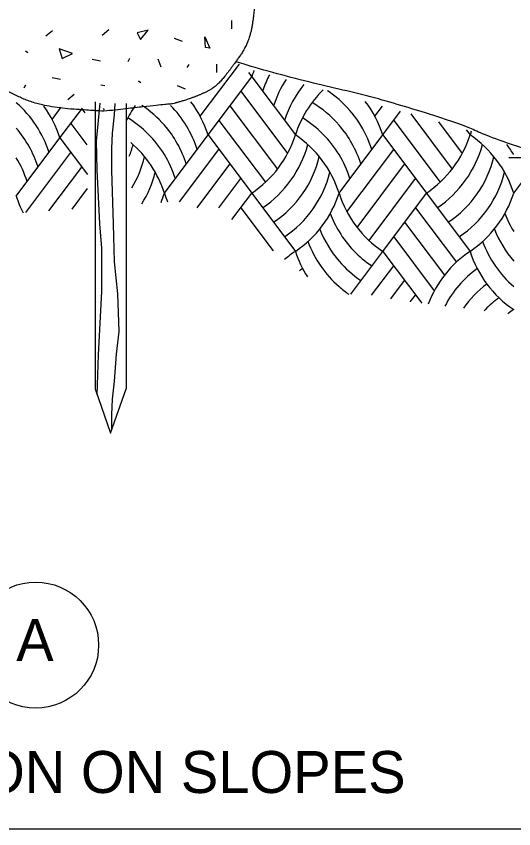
# Model space of a CAD drawing. Extents: x 99862 to 103680, y 99470 to 102076.
# Drawn here: x 101727.5 to 101964.3, y 99999.5 to 100386.5 of the extents above; entities that cross this region are included whole.
import ezdxf

# ---------------------------------------------------------------- set-up
doc = ezdxf.new("R2010")
doc.units = 0
for name, color, linetype in [('Level 1', 7, 'Continuous'), ('Level 13', 7, 'Continuous'), ('Level 2', 7, 'Continuous'), ('Level 20', 7, 'Continuous'), ('Level 3', 7, 'Continuous'), ('Level 4', 7, 'Continuous')]:
    doc.layers.add(name, color=color, linetype=linetype)

msp = doc.modelspace()

# ---------------------------------------------------------------- linework, layer by layer
at = {"layer": 'Level 1'}
msp.add_lwpolyline([(99862, 99999.5), (103151, 99999.5), (103151, 102075.5), (99862, 102075.5)], close=True, dxfattribs=at)
at = {"layer": 'Level 13'}
for p, q in [((101815.06, 100338.81), (101833.69, 100363.65)), ((101838.12, 100359.62), (101839.59, 100357.66)), ((101818.8, 100329.94), (101839.59, 100357.66)), ((101839.59, 100357.66), (101860.38, 100329.94)), ((101834.4, 100350.73), (101856.64, 100321.07)), ((101744.52, 100337.37), (101748.91, 100343.22)), ((101748.27, 100328.5), (101758.97, 100342.77)), ((101829.2, 100343.8), (101851.82, 100313.64)), ((101898.22, 100338.81), (101901.86, 100343.67)), ((101758.66, 100342.36), (101760.07, 100340.48)), ((101768.89, 100342.58), (101769.4, 100341.9)), ((101901.96, 100329.94), (101910.47, 100341.28)), ((101915.26, 100339.93), (101934.97, 100313.64)), ((101753.47, 100335.43), (101761.11, 100325.24)), ((101824, 100336.87), (101846.11, 100307.39)), ((101907.16, 100336.87), (101929.26, 100307.39)), ((101928.49, 100336.15), (101939.79, 100321.07)), ((101941.72, 100332.36), (101943.54, 100329.94)), ((101727.48, 100300.78), (101748.27, 100328.5)), ((101748.27, 100328.5), (101761.34, 100311.08)), ((101798.01, 100302.22), (101818.8, 100329.94)), ((101818.8, 100329.94), (101839.59, 100302.22)), ((101881.17, 100302.22), (101901.96, 100329.94)), ((101901.96, 100329.94), (101922.75, 100302.22)), ((101732.01, 100292.96), (101753.47, 100321.57)), ((101805.25, 100298.01), (101824, 100323.01)), ((101884.91, 100293.35), (101907.16, 100323.01)), ((101813.56, 100295.23), (101829.2, 100316.08)), ((101889.74, 100285.92), (101912.35, 100316.08)), ((101964.33, 100302.22), (101976.89, 100318.97)), ((101743.03, 100293.79), (101758.66, 100314.64)), ((101823.96, 100295.23), (101834.4, 100309.15)), ((101895.44, 100279.67), (101917.55, 100309.15)), ((101754.05, 100294.62), (101761.36, 100304.38)), ((101830.19, 100289.69), (101839.59, 100302.22)), ((101839.59, 100302.22), (101860.38, 100274.5)), ((101901.96, 100274.5), (101922.75, 100302.22)), ((101922.75, 100302.22), (101943.54, 100274.5)), ((101834.4, 100295.29), (101849.81, 100274.74)), ((101917.55, 100295.29), (101937.02, 100269.33)), ((101912.35, 100288.36), (101931.31, 100263.08)), ((101907.16, 100281.43), (101926.49, 100255.65)), ((101886.69, 100254.14), (101901.96, 100274.5)), ((101901.96, 100274.5), (101920.52, 100249.76)), ((101896.64, 100253.56), (101907.16, 100267.57)), ((101905.82, 100251.94), (101912.35, 100260.64)), ((101915.08, 100250.42), (101917.55, 100253.71))]:
    msp.add_line(p, q, dxfattribs=at)
for centre, start, end in [((101889.73, 100341.71), 158.9368, 162.3566), ((101894.92, 100334.78), 153.1077, 154.2266), ((101894.92, 100334.78), 154.2265, 162.3566), ((101900.12, 100327.85), 147.1557, 162.3566), ((101905.32, 100320.92), 141.0028, 162.3566), ((101910.52, 100313.99), 134.5463, 162.3566), ((101846.63, 100307.07), 48.9597, 56.448), ((101846.63, 100307.07), 17.6434, 48.9597), ((101692.94, 100305.62), 17.6434, 48.9597), ((101698.13, 100312.55), 17.6434, 36.1502), ((101827.36, 100313.99), 145.217, 154.7136), ((101758.28, 100300.14), 40.9413, 56.5027), ((101763.47, 100307.07), 17.6434, 44.603), ((101768.67, 100313.99), 17.6434, 37.0742), ((101841.43, 100300.14), 40.9413, 59.3021), ((101851.83, 100313.99), 17.6434, 37.3989), ((101753.08, 100293.21), 31.3316, 58.4874), ((101836.23, 100293.21), 31.3316, 58.4874), ((101687.74, 100298.69), 17.6434, 40.9414), ((101758.28, 100300.14), 17.6434, 40.9414), ((101841.43, 100300.14), 17.6434, 40.9414), ((101993.67, 100313.99), 160.3603, 162.3566), ((101810.25, 100345.89), 303.9036, 342.3566), ((101831.04, 100286.28), 17.6434, 56.0964), ((101893.4, 100345.89), 303.9036, 342.3566), ((101914.19, 100286.28), 17.6434, 56.0964), ((101732.29, 100338.96), 338.6376, 345.0113), ((101747.88, 100286.28), 17.6434, 49.6095), ((101815.44, 100338.96), 303.9036, 345.0113), ((101898.6, 100338.96), 303.9036, 345.0113), ((101919.39, 100293.21), 31.3316, 37.7081), ((101737.49, 100332.03), 328.7287, 346.3199), ((101753.08, 100293.21), 17.6434, 31.3317), ((101820.64, 100332.03), 303.9036, 346.3199), ((101836.23, 100293.21), 17.6434, 31.3317), ((101903.8, 100332.03), 303.9036, 346.3199), ((101682.54, 100291.76), 17.6434, 31.3317), ((101742.68, 100325.1), 327.8788, 345.7713), ((101825.84, 100325.1), 303.9036, 345.7713), ((101909, 100325.1), 303.9036, 345.7713), ((101777.61, 100316.73), 197.6435, 206.9683), ((101747.88, 100318.17), 337.239, 342.3566), ((101848.15, 100318.17), 197.6435, 202.4815), ((101831.04, 100318.17), 303.9036, 342.3566), ((101931.3, 100318.17), 197.6435, 236.0964), ((101914.19, 100318.17), 303.9036, 342.3566), ((101926.11, 100311.24), 200.8778, 211.332), ((102009.26, 100311.24), 200.8778, 211.332), ((101920.91, 100304.31), 201.4344, 220.9416), ((102004.07, 100304.31), 201.4344, 220.9416), ((101926.11, 100311.24), 211.3319, 236.0964), ((101915.71, 100297.38), 200.2432, 228.9599), ((101998.87, 100297.38), 200.2432, 228.9599), ((101889.73, 100230.84), 123.9036, 130.946), ((101910.52, 100290.45), 197.6434, 212.3563), ((101972.88, 100230.84), 123.9036, 159.3611), ((101993.67, 100290.45), 197.6434, 236.0964), ((101920.91, 100304.31), 220.9415, 236.0964), ((101894.92, 100223.91), 126.3063, 128.3248), ((101978.08, 100223.91), 126.3063, 152.2203), ((101915.71, 100297.38), 228.9599, 235.4271), ((101983.28, 100216.98), 127.1006, 144.72), ((101988.47, 100210.05), 126.331, 135.7128), ((101988.47, 100210.05), 135.7127, 136.6423), ((101993.67, 100203.12), 123.9036, 127.6088)]:
    msp.add_arc(centre, 52.61, start, end, dxfattribs=at)
msp.add_open_spline([(102171.14, 100258.73), (102114.61, 100273.61), (102070.74, 100297.76), (102046.64, 100300.07), (102022.69, 100307.39), (101953.56, 100327.81), (101945.33, 100332.95), (101925.24, 100339.53), (101896.48, 100348.47), (101865.9, 100355.06), (101840.84, 100362), (101832.15, 100364.83)], degree=3, dxfattribs=at)
at = {"layer": 'Level 2'}
for p, q in [((101829.9, 100384.49), (101829.9, 100380.44)), ((101829.9, 100384.49), (101829.9, 100380.44)), ((101741.58, 100377.09), (101744.66, 100379.73)), ((101741.58, 100377.09), (101744.66, 100379.73)), ((101768.45, 100377.5), (101771.52, 100380.14)), ((101768.45, 100377.5), (101771.52, 100380.14)), ((101802.66, 100376.08), (101806.42, 100374.57)), ((101802.66, 100376.08), (101806.42, 100374.57)), ((101731.9, 100370.08), (101732.96, 100369.23)), ((101731.9, 100370.08), (101732.96, 100369.23)), ((101763.64, 100366.01), (101767.63, 100365.29)), ((101763.64, 100366.01), (101767.63, 100365.29)), ((101781.46, 100366.28), (101780.62, 100364.8)), ((101781.46, 100366.28), (101780.62, 100364.8)), ((101796.42, 100362.25), (101795.05, 100366.07)), ((101796.42, 100362.25), (101795.05, 100366.07)), ((101809.58, 100363.53), (101808.74, 100362.05)), ((101809.58, 100363.53), (101808.74, 100362.05)), ((101822.78, 100363.72), (101822.78, 100359.67)), ((101822.78, 100363.72), (101822.78, 100359.67)), ((101744.51, 100357.25), (101748.5, 100356.53)), ((101744.51, 100357.25), (101748.5, 100356.53)), ((101785.68, 100355.72), (101786.74, 100354.87)), ((101785.68, 100355.72), (101786.74, 100354.87)), ((101731.93, 100353.67), (101731.09, 100352.19)), ((101731.93, 100353.67), (101731.09, 100352.19)), ((101769.64, 100353.4), (101767.75, 100353.61)), ((101769.64, 100353.4), (101767.75, 100353.61)), ((101804.08, 100353.47), (101807.84, 100351.97)), ((101804.08, 100353.47), (101807.84, 100351.97)), ((101751.96, 100346.75), (101755.04, 100349.39)), ((101751.96, 100346.75), (101755.04, 100349.39)), ((101764.98, 100345.65), (101764.98, 100208.98)), ((101764.98, 100345.65), (101764.98, 100208.98)), ((101779.83, 100344.88), (101779.83, 100208.98)), ((101779.83, 100344.88), (101779.83, 100208.98)), ((101764.98, 100208.98), (101772.41, 100187.84)), ((101764.98, 100208.98), (101772.41, 100187.84)), ((101772.41, 100187.84), (101779.83, 100208.98)), ((101772.41, 100187.84), (101779.83, 100208.98))]:
    msp.add_line(p, q, dxfattribs=at)
for points in [[(101785.08, 100378.61), (101786.56, 100375.44), (101790.35, 100379.88)], [(101785.08, 100378.61), (101786.56, 100375.44), (101790.35, 100379.88)], [(101817.18, 100376.62), (101819.71, 100371.34), (101817.6, 100371.55)], [(101817.18, 100376.62), (101819.71, 100371.34), (101817.6, 100371.55)], [(101747.91, 100370.92), (101749.39, 100366.28), (101754.24, 100368.81)], [(101747.91, 100370.92), (101749.39, 100366.28), (101754.24, 100368.81)]]:
    msp.add_lwpolyline(points, close=True, dxfattribs=at)
for points in [[(101765.97, 100313.32), (101765.73, 100327.01), (101767.4, 100345)], [(101765.97, 100313.32), (101765.73, 100327.01), (101767.4, 100345)], [(101773.83, 100287.59), (101772.98, 100313.17), (101772.98, 100323.55), (101773.29, 100330.82), (101774.23, 100339.47), (101774.63, 100344.92)], [(101773.83, 100287.59), (101772.98, 100313.17), (101772.98, 100323.55), (101773.29, 100330.82), (101774.23, 100339.47), (101774.63, 100344.92)], [(101773.83, 100287.59), (101772.98, 100313.17), (101772.98, 100323.55), (101773.29, 100330.82), (101774.23, 100339.47), (101774.63, 100344.92)], [(101773.83, 100287.59), (101772.98, 100313.17), (101772.98, 100323.55), (101773.29, 100330.82), (101774.23, 100339.47), (101774.63, 100344.92)], [(101773.83, 100287.59), (101772.98, 100313.17), (101772.98, 100323.55), (101773.29, 100330.82), (101774.23, 100339.47), (101774.63, 100344.92)], [(101773.83, 100287.59), (101772.98, 100313.17), (101772.98, 100323.55), (101773.29, 100330.82), (101774.23, 100339.47), (101774.63, 100344.92)], [(101773.83, 100287.59), (101772.98, 100313.17), (101772.98, 100323.55), (101773.29, 100330.82), (101774.23, 100339.47), (101774.63, 100344.92)], [(101773.83, 100287.59), (101772.98, 100313.17), (101772.98, 100323.55), (101773.29, 100330.82), (101774.23, 100339.47), (101774.63, 100344.92)], [(101767.3, 100287.59), (101765.97, 100313.34)], [(101767.3, 100287.59), (101765.97, 100313.34)], [(101767.3, 100287.59), (101765.97, 100313.34)], [(101767.3, 100287.59), (101765.97, 100313.34)], [(101767.3, 100287.59), (101765.97, 100313.34)], [(101767.3, 100287.59), (101765.97, 100313.34)], [(101767.3, 100287.59), (101765.97, 100313.34)], [(101767.3, 100287.59), (101765.97, 100313.34)], [(101765.96, 100206.2), (101766.67, 100225.2), (101768.24, 100255.31), (101768.24, 100276.07), (101767.3, 100287.59)], [(101765.96, 100206.2), (101766.67, 100225.2), (101768.24, 100255.31), (101768.24, 100276.07), (101767.3, 100287.59)], [(101772.98, 100189.47), (101772.98, 100196.83), (101773.29, 100204.1), (101774.23, 100212.75), (101775.17, 100225.55), (101776.42, 100236.28), (101775.8, 100254.27), (101774.23, 100269.49), (101773.83, 100287.59)], [(101772.98, 100189.47), (101772.98, 100196.83), (101773.29, 100204.1), (101774.23, 100212.75), (101775.17, 100225.55), (101776.42, 100236.28), (101775.8, 100254.27), (101774.23, 100269.49), (101773.83, 100287.59)]]:
    msp.add_lwpolyline(points, dxfattribs=at)
at = {"layer": 'Level 20'}
msp.add_circle((101736.7, 100086.98), 30, dxfattribs=at)
msp.add_circle((101736.7, 100086.98), 30, dxfattribs=at)
at = {"layer": 'Level 3'}
msp.add_line((102240.59, 100319.1), (101961.95, 100319.1), dxfattribs=at)
msp.add_line((102240.59, 100319.1), (101961.95, 100319.1), dxfattribs=at)
at = {"layer": 'Level 4'}
msp.add_open_spline([(101769.22, 100341.21), (101799.01, 100344.6), (101801.85, 100344.6), (101813.62, 100348.34), (101822.44, 100352.65), (101829.16, 100360.79), (101838.73, 100374.3), (101841.15, 100391.85), (101841.15, 100402.73), (101843.37, 100418.5), (101832.05, 100451.88), (101812.29, 100468.32), (101800.09, 100474.64), (101791.04, 100478.16), (101778.21, 100481), (101772.21, 100481.37), (101750.99, 100479.1), (101734.03, 100473.42), (101711.81, 100455.11), (101700.95, 100442.11), (101691.23, 100409.12), (101697.67, 100363.6), (101721.04, 100351.59), (101739.7, 100343.19), (101769.22, 100341.21), (101769.22, 100341.21)], degree=2, dxfattribs=at)

# ---------------------------------------------------------------- texts
at = {"layer": 'Level 20'}
for s, p in [('A', (101727.46, 100079.36)), ('A', (101727.46, 100079.36)), ('WATTLE INSTALLATION ON SLOPES', (101444.72, 100016.53))]:
    msp.add_text(s, height=20, dxfattribs=at).set_placement(p)

doc.saveas('drawing.dxf')
